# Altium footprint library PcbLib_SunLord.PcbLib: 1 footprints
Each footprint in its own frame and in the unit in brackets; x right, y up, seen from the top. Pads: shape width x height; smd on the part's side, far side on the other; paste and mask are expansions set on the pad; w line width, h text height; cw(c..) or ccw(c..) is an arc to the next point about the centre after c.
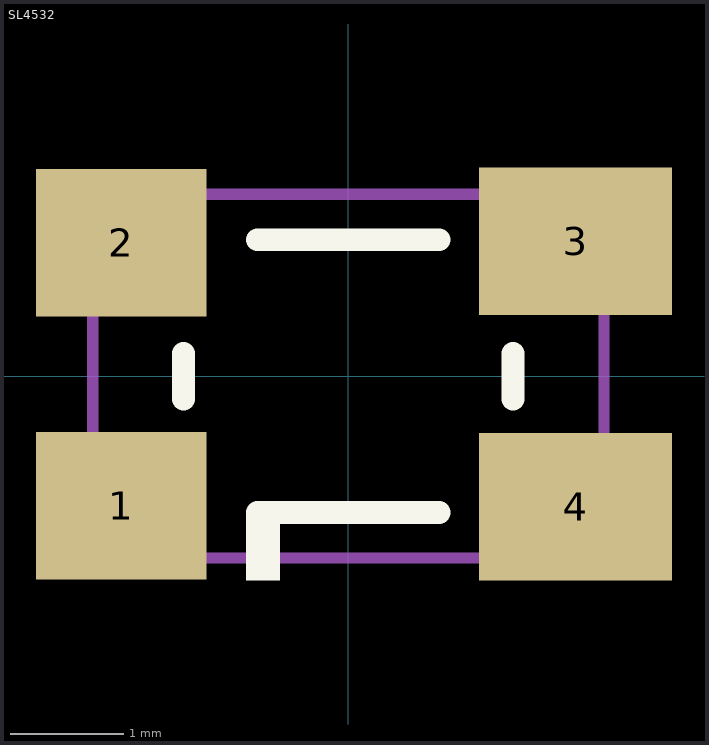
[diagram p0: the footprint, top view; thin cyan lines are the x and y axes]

## SL4532 [mm] "SMD, 4-Leads, Body 4.5 x 3.2mm"
height 3.6
pads (4):
  rect 1.5x1.3 smd: 1(-2,-1.141) 2(-2,1.173)
  rect 1.7x1.3 smd: 3(2,1.187) 4(2,-1.15)
Top Overlay:
  rectangle: -0.9,-1.8 -0.6,-1.2
  lines w0.2: -0.8,-1.2 0.8,-1.2 ; -0.8,1.2 0.8,1.2
  lines w0.203: -1.45,-0.2 -1.45,0.2 ; 1.45,-0.2 1.45,0.2
M6 Assembly Bottom:
  lines w0.1: -2.25,1.6 -2.25,-1.6 2.238,-1.6 ; -2.238,1.6 2.25,1.6 2.25,-1.6
  text ".Designator" at -0.9,-0.2 h0.5
3D body: height 3.45, standoff 0, extent -2.25,-1.6 2.25,1.6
